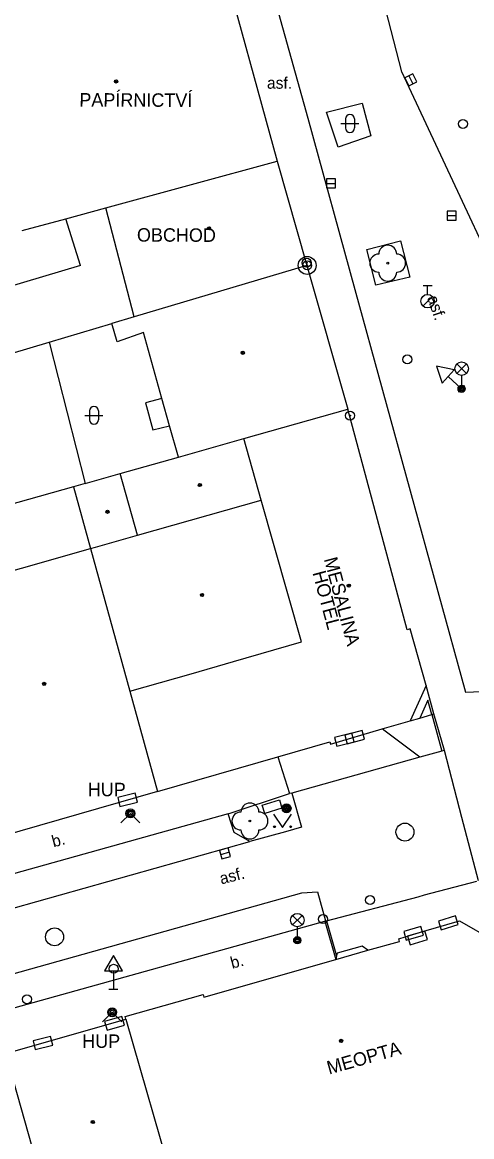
# Model space of a CAD drawing. Extents: x -595546 to -593986, y -1160845 to -1159202.
# Drawn here: x -595424.8 to -595399.7, y -1160706.8 to -1160644.7 of the extents above; entities that cross this region are included whole.
import ezdxf

# ---------------------------------------------------------------- set-up
doc = ezdxf.new("R2010")
doc.units = 0
for name, color, linetype in [('DOP - rozhrani ploch obecne', 7, 'Continuous'), ('Level 22', 7, 'Continuous'), ('Level 24', 7, 'Continuous'), ('Level 25', 7, 'Continuous'), ('Level 27', 7, 'Continuous'), ('Level 28', 7, 'Continuous'), ('Level 31', 7, 'Continuous'), ('Level 33', 7, 'Continuous'), ('Level 34', 7, 'Continuous'), ('Level 36', 7, 'Continuous'), ('Level 39', 7, 'Continuous'), ('slaboproud - povrch.  znaky a tel. budka skut. velikost', 7, 'Continuous'), ('Specificka linie pasportu komunikaci', 7, 'Continuous'), ('TM - budovy zdene_ betonove - VN', 7, 'Continuous'), ('TM - budovy zdene_ betonove - VP', 7, 'Continuous'), ('TM - komunikace - VP', 7, 'Continuous'), ('TM - letecke snimky - pomocna linie', 7, 'Continuous'), ('TM - popis objektu', 7, 'Continuous'), ('TM - popis povrchu', 7, 'Continuous'), ('TM - rozhrani ploch obecne - VP', 7, 'Continuous')]:
    doc.layers.add(name, color=color, linetype=linetype)

msp = doc.modelspace()

# ---------------------------------------------------------------- linework, layer by layer
at = {"layer": 'DOP - rozhrani ploch obecne'}
for points in [[(-595423.27, -1160662.52), (-595421.27, -1160670.4)], [(-595421.91, -1160670.59), (-595430.64, -1160673.05)]]:
    msp.add_lwpolyline(points, dxfattribs=at)
at = {"layer": 'Level 22'}
for centre in [(-595404.4, -1160658.12), (-595412.08, -1160689.22)]:
    msp.add_circle(centre, 0.05, dxfattribs=at)
for centre, start, end in [((-595404.4, -1160657.62), 0, 180), ((-595404.9, -1160658.12), 90, 270), ((-595403.9, -1160658.12), 270, 90), ((-595404.4, -1160658.62), 180, 0), ((-595412.58, -1160689.22), 90, 270), ((-595412.08, -1160688.72), 0, 180), ((-595411.58, -1160689.22), 270, 90), ((-595412.08, -1160689.72), 180, 0)]:
    msp.add_arc(centre, 0.5, start, end, dxfattribs=at)
at = {"layer": 'Level 24'}
for points in [[(-595407.245, -1160685.054), (-595406.274, -1160684.811), (-595406.395, -1160684.326), (-595407.366, -1160684.569)], [(-595406.668, -1160684.912), (-595405.702, -1160684.651), (-595405.832, -1160684.168), (-595406.798, -1160684.429)], [(-595419.325, -1160688.403), (-595418.355, -1160688.163), (-595418.475, -1160687.677), (-595419.445, -1160687.917)], [(-595401.423, -1160695.287), (-595400.468, -1160694.99), (-595400.617, -1160694.513), (-595401.572, -1160694.81)], [(-595403.371, -1160695.859), (-595402.41, -1160695.581), (-595402.549, -1160695.101), (-595403.51, -1160695.379)], [(-595403.146, -1160696.125), (-595402.189, -1160695.834), (-595402.334, -1160695.355), (-595403.291, -1160695.646)], [(-595420.038, -1160700.882), (-595419.079, -1160700.597), (-595419.222, -1160700.118), (-595420.181, -1160700.403)], [(-595424.047, -1160701.951), (-595423.075, -1160701.714), (-595423.193, -1160701.229), (-595424.165, -1160701.466)]]:
    msp.add_lwpolyline(points, close=True, dxfattribs=at)
at = {"layer": 'Level 25'}
for centre, radius in [((-595408.92, -1160658.1), 0.25), ((-595408.89, -1160658.25), 0.25), ((-595408.92, -1160658.1), 0.0303), ((-595408.89, -1160658.25), 0.0303), ((-595406.5, -1160666.62), 0.25), ((-595406.5, -1160666.62), 0.0303), ((-595410.04, -1160688.51), 0.25), ((-595410.04, -1160688.51), 0.2), ((-595410.04, -1160688.51), 0.15), ((-595410.04, -1160688.51), 0.1), ((-595410.04, -1160688.51), 0.05)]:
    msp.add_circle(centre, radius, dxfattribs=at)
at = {"layer": 'Level 27'}
for p, q in [((-595403.223, -1160647.677), (-595402.997, -1160648.123)), ((-595407.81, -1160653.68), (-595407.31, -1160653.68)), ((-595401.08, -1160655.47), (-595400.58, -1160655.47)), ((-595413.229, -1160690.962), (-595413.711, -1160691.098))]:
    msp.add_line(p, q, dxfattribs=at)
for points in [[(-595403.446, -1160647.79), (-595403.22, -1160648.236), (-595402.774, -1160648.01), (-595403, -1160647.564)], [(-595407.81, -1160653.93), (-595407.31, -1160653.93), (-595407.31, -1160653.43), (-595407.81, -1160653.43)], [(-595401.08, -1160655.72), (-595400.58, -1160655.72), (-595400.58, -1160655.22), (-595401.08, -1160655.22)], [(-595413.297, -1160690.722), (-595413.778, -1160690.857), (-595413.643, -1160691.338), (-595413.162, -1160691.203)]]:
    msp.add_lwpolyline(points, close=True, dxfattribs=at)
for centre in [(-595408.89, -1160658.25), (-595403.44, -1160689.84), (-595422.97, -1160695.68)]:
    msp.add_circle(centre, 0.5, dxfattribs=at)
at = {"layer": 'Level 28'}
for p, q in [((-595402.43, -1160659.365), (-595401.93, -1160659.365)), ((-595402.18, -1160659.865), (-595402.18, -1160659.365)), ((-595402.438, -1160660.512), (-595401.908, -1160659.982))]:
    msp.add_line(p, q, dxfattribs=at)
for centre, radius in [((-595400.21, -1160650.36), 0.25), ((-595402.18, -1160660.24), 0.375), ((-595403.31, -1160663.49), 0.25), ((-595405.38, -1160693.63), 0.25), ((-595408.01, -1160694.69), 0.25), ((-595419.68, -1160697.46), 0.25), ((-595424.51, -1160699.16), 0.25)]:
    msp.add_circle(centre, radius, dxfattribs=at)
at = {"layer": 'Level 31'}
for points in [[(-595419.27, -1160689.33), (-595418.74, -1160688.8), (-595418.21, -1160689.33)], [(-595420.29, -1160700.41), (-595419.76, -1160699.88), (-595419.23, -1160700.41)]]:
    msp.add_lwpolyline(points, dxfattribs=at)
for centre, radius in [((-595418.74, -1160688.8), 0.25), ((-595418.74, -1160688.8), 0.18), ((-595418.74, -1160688.8), 0.11), ((-595419.76, -1160699.88), 0.25), ((-595419.76, -1160699.88), 0.18), ((-595419.76, -1160699.88), 0.11)]:
    msp.add_circle(centre, radius, dxfattribs=at)
at = {"layer": 'Level 33'}
for p, q in [((-595400.545, -1160664.27), (-595400.015, -1160663.74)), ((-595400.545, -1160663.74), (-595400.015, -1160664.27)), ((-595400.28, -1160664.38), (-595400.28, -1160665.13)), ((-595409.705, -1160695.01), (-595409.175, -1160694.48)), ((-595409.705, -1160694.48), (-595409.175, -1160695.01)), ((-595409.44, -1160695.12), (-595409.44, -1160695.87))]:
    msp.add_line(p, q, dxfattribs=at)
for centre, radius in [((-595400.28, -1160664.005), 0.375), ((-595400.28, -1160665.13), 0.2), ((-595400.28, -1160665.13), 0.145), ((-595400.28, -1160665.13), 0.0876), ((-595409.44, -1160694.745), 0.375), ((-595409.44, -1160695.87), 0.2), ((-595409.44, -1160695.87), 0.145), ((-595409.44, -1160695.87), 0.0876)]:
    msp.add_circle(centre, radius, dxfattribs=at)
at = {"layer": 'Level 34'}
for p, q in [((-595401.033, -1160664.445), (-595400.28, -1160665.13)), ((-595400.448, -1160665.315), (-595400.112, -1160664.945)), ((-595419.69, -1160697.582), (-595419.69, -1160698.6)), ((-595419.94, -1160698.6), (-595419.44, -1160698.6))]:
    msp.add_line(p, q, dxfattribs=at)
for points in [[(-595401.37, -1160664.815), (-595400.697, -1160664.075), (-595401.674, -1160663.863)], [(-595420.19, -1160697.582), (-595419.19, -1160697.582), (-595419.69, -1160696.716)]]:
    msp.add_lwpolyline(points, close=True, dxfattribs=at)
at = {"layer": 'Level 36'}
for p, q in [((-595406.756, -1160650.086), (-595406.756, -1160650.586)), ((-595406.256, -1160650.086), (-595406.256, -1160650.586)), ((-595407.006, -1160650.336), (-595406.006, -1160650.336)), ((-595421.026, -1160666.356), (-595421.026, -1160666.856)), ((-595420.526, -1160666.356), (-595420.526, -1160666.856)), ((-595421.276, -1160666.606), (-595420.276, -1160666.606))]:
    msp.add_line(p, q, dxfattribs=at)
msp.add_lwpolyline([(-595410.76, -1160688.84), (-595410.26, -1160689.59), (-595409.76, -1160688.84)], dxfattribs=at)
for centre in [(-595410.71, -1160689.54), (-595409.811, -1160689.54)]:
    msp.add_circle(centre, 0.05, dxfattribs=at)
for centre, start, end in [((-595406.506, -1160650.086), 0, 180), ((-595406.506, -1160650.586), 180, 0), ((-595420.776, -1160666.356), 0, 180), ((-595420.776, -1160666.856), 180, 0)]:
    msp.add_arc(centre, 0.25, start, end, dxfattribs=at)
at = {"layer": 'Level 39'}
for centre, radius in [((-595419.54, -1160647.99), 0.09), ((-595419.54, -1160647.99), 0.0398), ((-595414.36, -1160656.18), 0.09), ((-595414.36, -1160656.18), 0.0398), ((-595412.48, -1160663.12), 0.09), ((-595412.48, -1160663.12), 0.0398), ((-595414.87, -1160670.49), 0.09), ((-595414.87, -1160670.49), 0.0398), ((-595420.02, -1160671.98), 0.09), ((-595420.02, -1160671.98), 0.0398), ((-595406.57, -1160676.1), 0.09), ((-595406.57, -1160676.1), 0.0398), ((-595414.75, -1160676.62), 0.09), ((-595414.75, -1160676.62), 0.0398), ((-595423.55, -1160681.58), 0.09), ((-595423.55, -1160681.58), 0.0398), ((-595407, -1160701.48), 0.09), ((-595407, -1160701.48), 0.0398), ((-595420.84, -1160706), 0.09), ((-595420.84, -1160706), 0.0398)]:
    msp.add_circle(centre, radius, dxfattribs=at)
at = {"layer": 'slaboproud - povrch.  znaky a tel. budka skut. velikost'}
msp.add_lwpolyline([(-595411.4, -1160688.33), (-595410.44, -1160688.04), (-595410.3, -1160688.51), (-595411.25, -1160688.81), (-595411.4, -1160688.33)], dxfattribs=at)
at = {"layer": 'Specificka linie pasportu komunikaci'}
for points in [[(-595401.94, -1160683.28), (-595402.16, -1160682.49), (-595402.61, -1160683.48)], [(-595401.94, -1160683.28), (-595401.38, -1160685.33)], [(-595401.23, -1160685.29), (-595401.83, -1160683.25)], [(-595402.61, -1160685.67), (-595404.62, -1160684.16), (-595404.71, -1160684.09)], [(-595410.53, -1160685.64), (-595409.87, -1160687.68)]]:
    msp.add_lwpolyline(points, dxfattribs=at)
at = {"layer": 'TM - budovy zdene_ betonove - VN'}
for points in [[(-595401.83, -1160683.25), (-595402.26, -1160681.66)], [(-595403.15, -1160683.64), (-595402.61, -1160683.48)], [(-595402.61, -1160683.48), (-595401.94, -1160683.28)], [(-595401.94, -1160683.28), (-595401.83, -1160683.25)]]:
    msp.add_lwpolyline(points, dxfattribs=at)
at = {"layer": 'TM - budovy zdene_ betonove - VP'}
for points in [[(-595413.86, -1160640.46), (-595410.56, -1160652.44)], [(-595420.12, -1160655.04), (-595410.56, -1160652.44)], [(-595410.56, -1160652.44), (-595408.91, -1160658.26)], [(-595422.34, -1160655.65), (-595420.12, -1160655.04)], [(-595418.53, -1160661.12), (-595420.12, -1160655.04)], [(-595424.78, -1160656.31), (-595422.34, -1160655.65)], [(-595421.53, -1160658.25), (-595429.14, -1160660.52)], [(-595408.91, -1160658.26), (-595418.53, -1160661.12)], [(-595408.91, -1160658.26), (-595406.63, -1160666.26)], [(-595423.27, -1160662.52), (-595419.78, -1160661.48)], [(-595418.53, -1160661.12), (-595419.78, -1160661.48)], [(-595419.48, -1160662.51), (-595419.78, -1160661.48)], [(-595418.02, -1160661.99), (-595419.48, -1160662.51)], [(-595416.99, -1160665.67), (-595418.02, -1160661.99)], [(-595427.34, -1160663.73), (-595423.27, -1160662.52)], [(-595416.56, -1160667.19), (-595416.99, -1160665.67)], [(-595412.42, -1160667.9), (-595406.63, -1160666.26)], [(-595403.32, -1160678.56), (-595406.63, -1160666.26)], [(-595416.07, -1160668.93), (-595416.56, -1160667.19)], [(-595416.07, -1160668.93), (-595412.42, -1160667.9)], [(-595411.45, -1160671.33), (-595412.42, -1160667.9)], [(-595419.31, -1160669.85), (-595416.07, -1160668.93)], [(-595421.27, -1160670.4), (-595419.31, -1160669.85)], [(-595418.35, -1160673.29), (-595419.31, -1160669.85)], [(-595421.27, -1160670.4), (-595421.91, -1160670.59)], [(-595421.91, -1160670.59), (-595420.96, -1160674.03)], [(-595418.35, -1160673.29), (-595411.45, -1160671.33)], [(-595409.21, -1160679.24), (-595411.45, -1160671.33)], [(-595420.68, -1160673.95), (-595418.35, -1160673.29)], [(-595428.67, -1160676.22), (-595420.96, -1160674.03)], [(-595420.96, -1160674.03), (-595420.68, -1160673.95)], [(-595420.96, -1160674.03), (-595418.77, -1160681.99)], [(-595403.15, -1160678.51), (-595403.32, -1160678.56)], [(-595402.26, -1160681.66), (-595403.15, -1160678.51)], [(-595412.99, -1160680.33), (-595409.21, -1160679.24)], [(-595415.35, -1160681.01), (-595412.99, -1160680.33)], [(-595418.77, -1160681.99), (-595415.35, -1160681.01)], [(-595418.77, -1160681.99), (-595417.24, -1160687.57)], [(-595402.26, -1160681.66), (-595403.15, -1160683.64)], [(-595404.71, -1160684.09), (-595403.15, -1160683.64)], [(-595407.59, -1160684.94), (-595404.71, -1160684.09)], [(-595410.53, -1160685.64), (-595407.63, -1160684.8)], [(-595407.63, -1160684.8), (-595407.59, -1160684.94)], [(-595417.24, -1160687.57), (-595410.53, -1160685.64)], [(-595417.24, -1160687.57), (-595426.03, -1160690.11)], [(-595402.38, -1160695.37), (-595400.4, -1160694.78)], [(-595400.4, -1160694.78), (-595398.52, -1160695.86)], [(-595403.43, -1160695.68), (-595402.38, -1160695.37)], [(-595405.5, -1160696.43), (-595403.74, -1160695.93)], [(-595403.78, -1160695.79), (-595403.43, -1160695.68)], [(-595403.74, -1160695.93), (-595403.78, -1160695.79)], [(-595407.3, -1160696.95), (-595405.5, -1160696.43)], [(-595414.65, -1160699.04), (-595407.3, -1160696.95)], [(-595419.04, -1160700.12), (-595414.69, -1160698.9)], [(-595414.69, -1160698.9), (-595414.65, -1160699.04)], [(-595425.69, -1160702.18), (-595419, -1160700.26)], [(-595419, -1160700.26), (-595419.04, -1160700.12)], [(-595419, -1160700.26), (-595416.3, -1160709.64)], [(-595422.71, -1160712.72), (-595425.69, -1160702.18)]]:
    msp.add_lwpolyline(points, dxfattribs=at)
at = {"layer": 'TM - komunikace - VP'}
for points in [[(-595403.61, -1160647.45), (-595407.5, -1160632.39), (-595408.24, -1160629.24), (-595408.35, -1160625.84)], [(-595395.5, -1160664.81), (-595403.61, -1160647.45)], [(-595402.61, -1160685.67), (-595409.74, -1160687.66)], [(-595401.38, -1160685.33), (-595402.61, -1160685.67)], [(-595401.23, -1160685.29), (-595401.38, -1160685.33)], [(-595400.26, -1160689.03), (-595401.23, -1160685.29)], [(-595409.74, -1160687.66), (-595409.21, -1160689.56), (-595410.1, -1160689.83), (-595412.09, -1160690.37)], [(-595413.3, -1160688.82), (-595427.8, -1160692.88)], [(-595412.09, -1160690.37), (-595412.95, -1160689.86), (-595413.3, -1160688.82)], [(-595399.34, -1160692.55), (-595400.26, -1160689.03)], [(-595402.34, -1160693.34), (-595399.44, -1160692.58)], [(-595407.81, -1160694.78), (-595402.71, -1160693.44)], [(-595402.71, -1160693.44), (-595402.34, -1160693.34)], [(-595461.62, -1160709.89), (-595444.57, -1160705.07), (-595426.44, -1160699.97), (-595407.91, -1160694.8)], [(-595407.91, -1160694.8), (-595407.86, -1160694.79)], [(-595407.86, -1160694.79), (-595407.81, -1160694.78)]]:
    msp.add_lwpolyline(points, dxfattribs=at)
at = {"layer": 'TM - letecke snimky - pomocna linie'}
for points in [[(-595421.53, -1160658.25), (-595422.34, -1160655.65)], [(-595427.93, -1160694.83), (-595412.09, -1160690.37)]]:
    msp.add_lwpolyline(points, dxfattribs=at)
at = {"layer": 'TM - rozhrani ploch obecne - VP'}
for points in [[(-595414.47, -1160629.94), (-595408.86, -1160650.04), (-595406.23, -1160659.6)], [(-595407.81, -1160649.71), (-595405.82, -1160649.21), (-595405.35, -1160651.03), (-595407.17, -1160651.66)], [(-595407.17, -1160651.66), (-595407.81, -1160649.71)], [(-595405.56, -1160657.36), (-595403.69, -1160656.87), (-595403.17, -1160658.9), (-595405.07, -1160659.35)], [(-595405.07, -1160659.35), (-595405.56, -1160657.36)], [(-595406.23, -1160659.6), (-595400.06, -1160682.03)], [(-595416.99, -1160665.67), (-595417.9, -1160665.9), (-595417.5, -1160667.42), (-595416.56, -1160667.19)], [(-595400.06, -1160682.03), (-595397.38, -1160681.92)], [(-595413.3, -1160688.82), (-595409.87, -1160687.68)], [(-595409.74, -1160687.66), (-595409.87, -1160687.68)], [(-595461.62, -1160707.98), (-595445.03, -1160703.3), (-595426.9, -1160698.18), (-595409.18, -1160693.23), (-595408.32, -1160693.17), (-595407.86, -1160694.79)], [(-595407.91, -1160694.8), (-595407.3, -1160696.95)], [(-595407.81, -1160694.78), (-595407.25, -1160696.73)], [(-595405.5, -1160696.43), (-595405.82, -1160696.19), (-595407.22, -1160696.58), (-595407.25, -1160696.73)], [(-595407.25, -1160696.73), (-595407.3, -1160696.95)]]:
    msp.add_lwpolyline(points, dxfattribs=at)

# ---------------------------------------------------------------- texts
at = {"layer": 'TM - popis objektu'}
for s, rotation, p in [('PAPÍRNICTVÍ', 359.78283, (-595421.59, -1160649.39)), ('OBCHOD', 359.78, (-595418.38, -1160656.92)), ('MESALINA', 285, (-595407.96, -1160674.62)), ('HOTEL', 285, (-595408.6, -1160675.38)), ('MEOPTA', 15.68999, (-595407.67, -1160703.36))]:
    msp.add_text(s, height=0.75, rotation=rotation, dxfattribs=at).set_placement(p)
for p in [(-595421.12, -1160687.84), (-595421.43, -1160701.87)]:
    msp.add_text('HUP', height=0.75, dxfattribs=at).set_placement(p)
at = {"layer": 'TM - popis povrchu'}
msp.add_text('asf.', height=0.65, dxfattribs=at).set_placement((-595411.13, -1160648.4))
for s, rotation, p in [('asf.', 289.12, (-595402.21, -1160660.05)), ('b.', 14.8144, (-595423.03, -1160690.69)), ('asf.', 14.03624, (-595413.68, -1160692.76)), ('b.', 14.8144, (-595413.07, -1160697.46))]:
    msp.add_text(s, height=0.65, rotation=rotation, dxfattribs=at).set_placement(p)

doc.saveas('drawing.dxf')
